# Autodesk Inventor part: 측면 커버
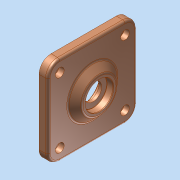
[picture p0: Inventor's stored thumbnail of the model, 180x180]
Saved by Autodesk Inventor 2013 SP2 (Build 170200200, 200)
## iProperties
Created: 2026-01
Part Number: 측면 커버
Material: Generic
Document SubType Name: Modeling
Designer: a
Density: 1 g/cm^3
Author: a
변환 표준: STEP AP214IS
전처리기: Build: 200, Release: 2013 SP2 Update 6 - Date: Thu 07/17/2014
전송 단위: 밀리미터
불확실성: 0.01
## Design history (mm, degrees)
node "측면 커버1"
node "솔리드1"
node "기준1"
